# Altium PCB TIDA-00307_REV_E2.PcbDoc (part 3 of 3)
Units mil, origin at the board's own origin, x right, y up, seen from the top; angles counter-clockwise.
Board outline 2360 x 3725 mil, 4 copper layers (Top Layer, L2_GND-PLANE, L3_PWR-PLANE, Bottom Layer), stack 90 mil thick; 312 components, 149 nets, 674 pads, 257 vias.
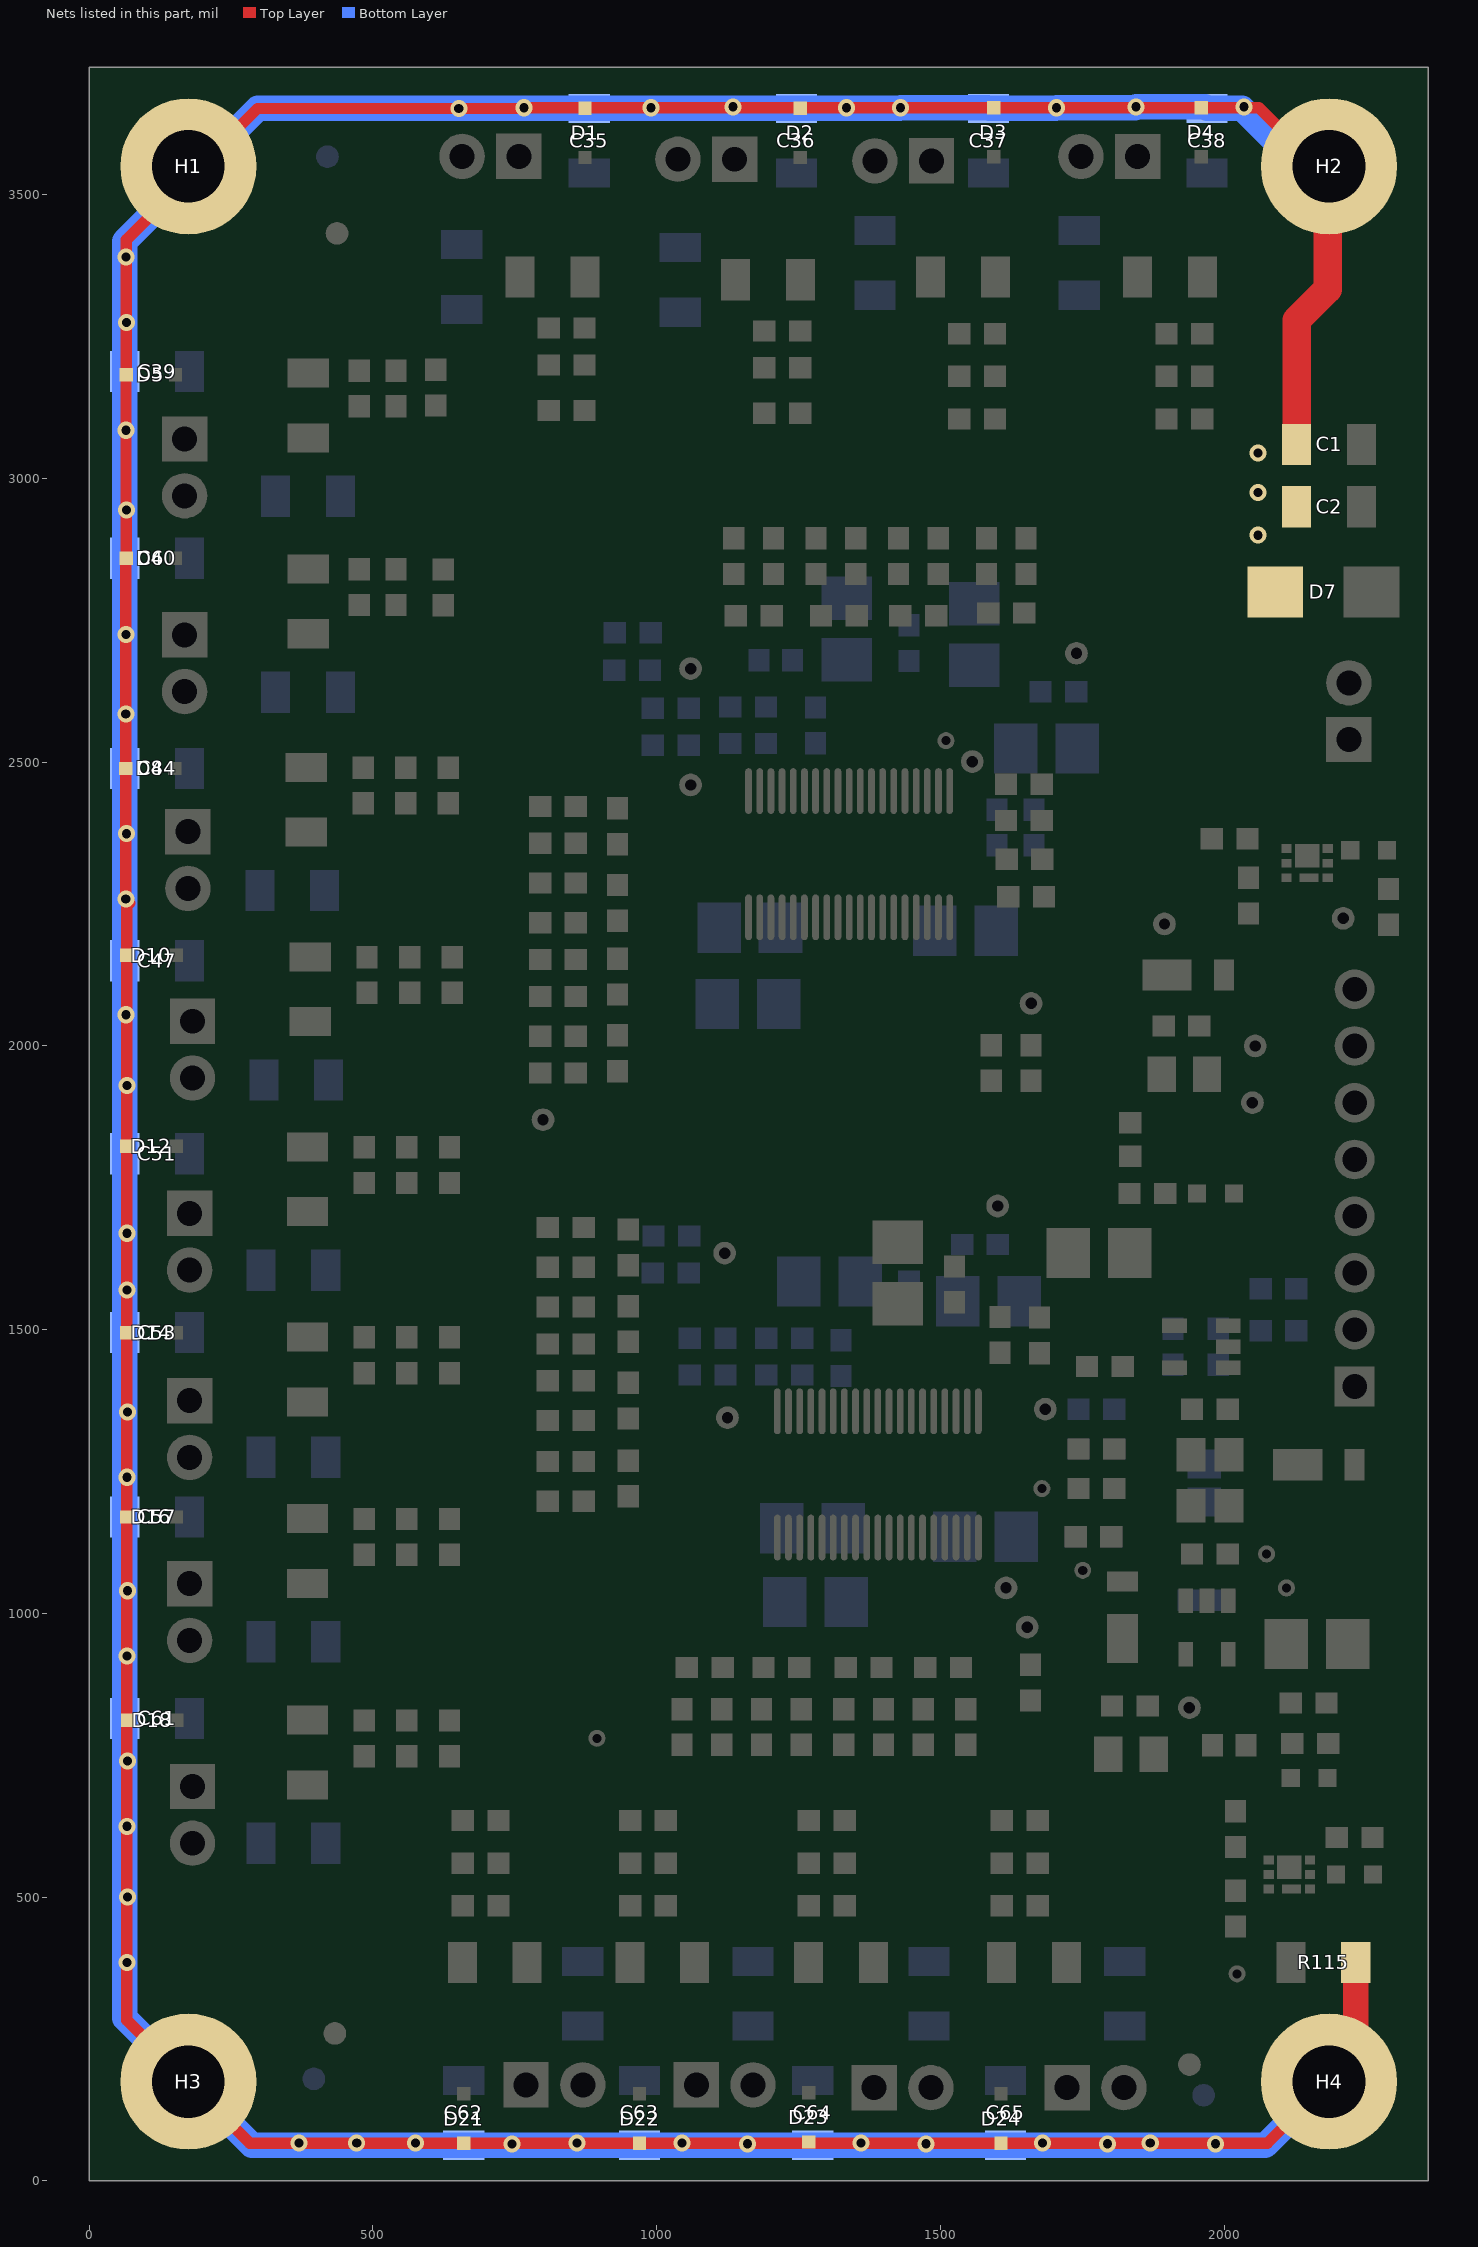
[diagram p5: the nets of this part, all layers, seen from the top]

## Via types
v1: diameter 30, hole 16, Top Layer to Bottom Layer, tented both sides, 155 vias
v2: diameter 24, hole 12, Top Layer to Bottom Layer, tented both sides, 102 vias

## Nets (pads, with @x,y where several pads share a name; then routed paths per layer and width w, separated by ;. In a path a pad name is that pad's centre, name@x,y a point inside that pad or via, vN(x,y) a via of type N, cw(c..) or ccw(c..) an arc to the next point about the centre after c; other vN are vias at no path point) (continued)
SGND1: C1.1 C2.1 C35.2 C36.2 C37.2 C38.2 C39.2 C40.2 C44.2 C47.2 C51.2 C53.2 C57.2 C61.2 C62.2 C63.2 C64.2 C65.2 D1.2 D2.2 D3.2 D4.2 D5.2 D6.2 D7.1 D8.2 D10.2 D12.2 D14.2 D16.2 D18.2 D21.2 D22.2 D23.2 D24.2 H1.1 H2.1 H3.1 H4.1 R115.2 | length 16058.1
  Top Layer w20: H2.1@2182.5,3532.5 2061.69,3653.31 D4.2@1960,3653.31 v1(1705,3653.31) D3.2@1594,3653.31 v1(1430,3653.31) v1(1335,3653.31) v1(990,3653.31) v1(766.5,3653.31) 765.28,3652.09 v1(651.5,3652.09) 297.09,3652.09 208,3563 65.69,3420.69 v1(65.69,3275) 65.69,3188.5 65,3187.8 v1(65,3085) 65,2945 v1(65.69,2944.31) D6.2@65.69,2859.5 64.69,2858.5 v1(64.69,2585) D8.2@64.69,2489 v1(64.69,2259) 71.69,2252 66.69,2247 D10.2@66.69,2160 v1(66.69,1930) D12.2@66.69,1823 v1(66.69,1670) D14.2@66.69,1495 v1(66.69,1240) D16.2@66.69,1170 v1(66.69,925) v1(66.69,625) v1(66.69,385) 66.69,283.31 H3.1@175,175 283.31,66.69 v1(370,66.69) v1(471.65,66.69) v1(575,66.69) D21.2@660,66.69 v1(860,66.69) D22.2@970,66.69 v1(1045,66.69) 1275,66.69 v1(1360,66.69) D24.2@1607,66.69 v1(1680,66.69) v1(1870,66.69) 2076.69,66.69 H4.1@2185,175
  Top Layer w45: H4.1@2185,175 2232.09,222.09 R115.2@2232.09,385
  Top Layer w50: C1.1@2127.91,3060 2127.91,3197.91 2127.91,3278.91 2182.5,3333.5 H2.1@2182.5,3532.5
  Bottom Layer w45: C40.2@62.91,2859.5 C39.2@62.91,3188.5 62.91,3417.91 208,3563 297.09,3652.09 v1(651.5,3652.09) C35.2@881.5,3652.09 C36.2@1246.5,3652.09 1428.78,3652.09 v1(1430,3653.31) 1583.78,3653.31 C37.2@1585,3652.09 1703.78,3652.09 v1(1705,3653.31) 1843.31,3653.31 v1(1845,3655) 1967.09,3655 C38.2@1970,3652.09 2032.09,3652.09 2159.17,3525 H2.1@2190,3525 ; C40.2@66.91,2859.5 62.91,2855.5 C44.2@62.91,2489 C47.2@62.91,2150 C51.2@62.91,1810 C53.2@62.91,1495 62.91,1240 C57.2@62.91,1170 62.91,925 C61.2@62.91,815 62.91,287.09 H3.1@175,175 287.09,62.91 575,62.91 C62.2@660,62.91 C63.2@970,62.91 1160,62.91 C64.2@1275,62.91 C65.2@1615,62.91 1795,62.91 2072.91,62.91 H4.1@2185,175
  other v1: 745,65 1160,65.47 1475,65.47 1795,65.47 1985,65.47 67.91,500 67.91,740 67.91,1040 67.91,1355 67.08,1570 65,2055 65.91,2374 65,2725 2060,2900 2060,2975 2060,3045 65,3390 1135,3655 2035,3655
pads on no net: FID1.1 FID2.1 FID3.1 FID4.1 FID5.1 FID6.1 U4.4

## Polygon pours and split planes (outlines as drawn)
SGND on Bottom Layer "Bottom Layer-No Net" (solid, remove dead copper, pour order 137): 410,1057.09 610,1057.09 630,1037.09 630,982.09 630,927.09 625,922.09 620,917.09 600,917.09 425,917.09 405,937.09 395,947.09 395,992.09 395,1042.09 410,1057.09
SGND on Bottom Layer "Bottom Layer-No Net" (solid, remove dead copper, pour order 142): 610,560 410,560 390,580 390,635 390,690 395,695 400,700 420,700 595,700 615,680 625,670 625,625 625,575 610,560
SGND on Bottom Layer "Bottom Layer-No Net" (solid, remove dead copper, pour order 141): 902.09,580 902.09,380 882.09,360 827.09,360 772.09,360 767.09,365 762.09,370 762.09,390 762.09,565 782.09,585 792.09,595 837.09,595 887.09,595 902.09,580
SGND on Bottom Layer "Bottom Layer-No Net" (solid, remove dead copper, pour order 140): 1212.09,580 1212.09,380 1192.09,360 1137.09,360 1082.09,360 1077.09,365 1072.09,370 1072.09,390 1072.09,565 1092.09,585 1102.09,595 1147.09,595 1197.09,595 1212.09,580
SGND on Bottom Layer "Bottom Layer-No Net" (solid, remove dead copper, pour order 139): 1517.09,580 1517.09,380 1497.09,360 1442.09,360 1387.09,360 1382.09,365 1377.09,370 1377.09,390 1377.09,565 1397.09,585 1407.09,595 1452.09,595 1502.09,595 1517.09,580
SGND on Bottom Layer "Bottom Layer-No Net" (solid, remove dead copper, pour order 138): 1872.09,585 1872.09,385 1852.09,365 1797.09,365 1742.09,365 1737.09,370 1732.09,375 1732.09,395 1732.09,570 1752.09,590 1762.09,600 1807.09,600 1857.09,600 1872.09,585
SGND on Bottom Layer "Bottom Layer-No Net" (solid, remove dead copper, pour order 128): 408,1373 548,1373 568,1353 568,1253 543,1228 428,1228 393,1260.09 393,1355.09
SGND on Bottom Layer "Bottom Layer-No Net" (solid, remove dead copper, pour order 129): 404,1704 544,1704 564,1684 564,1584 539,1559 424,1559 389,1591.09 389,1686.09
SGND on Bottom Layer "Bottom Layer-No Net" (solid, remove dead copper, pour order 105): 1605,1595 1740,1595 1770,1565 1775,1560 1775,1505 1775,1481.2 1756,1462.2 1753.25,1459.45 1674.06,1459.45 1625.55,1459.45 1605,1480 1600,1485 1600,1515 1600,1595
SGND on Bottom Layer "Bottom Layer-No Net" (solid, remove dead copper, pour order 97): 1729.33,2278.11 1588.61,2278.11 1576.35,2265.84 1564.33,2253.83 1564.33,2218.11 1564.33,2163.11 1574.33,2153.11 1579.33,2148.11 1634.33,2148.11 1714.33,2148.11 1724.33,2158.11 1754.33,2188.11 1754.33,2233.11 1754.33,2258.11 1734.33,2278.11 1729.33,2278.11
SGND on Bottom Layer "Bottom Layer-No Net" (solid, remove dead copper, pour order 94): 1100,1200 1250,1200 1260,1190 1260,1140 1260,985 1240,965 1235,960 1135,960 1100,960 1070,990 1065,995 1065,1120 1065,1170 1095,1200
SGND on Bottom Layer "Bottom Layer-No Net" (solid, remove dead copper, pour order 93): 1000,1385 1000.79,1384.21 1065,1384.21 1075.79,1395 1075,1395.79 1075,1445 1075,1540 1045,1570 1000,1570 995,1570 985,1560 980,1555 980,1500 980,1405 1000,1385
+5V_AVDD on Bottom Layer "Bottom Layer-No Net 1" (solid, remove dead copper, pour order 100): 1295,970 1295,1185 1305,1195 1345,1195 1415,1195 1430,1180 1445,1165 1445,1010 1445,975 1430,960 1420,950 1320,950 1315,950 1295,970
+3.3V on Bottom Layer "Bottom Layer-No Net 1" (solid, remove dead copper, pour order 104): 1460,975 1460,1165 1475,1180 1520,1180 1560,1180 1565,1175 1565,1115 1565,1005 1545,985 1530,970 1480,970 1465,970 1460,975
SGND on Bottom Layer "Bottom Layer-No Net" (solid, remove dead copper, pour order 110): 1255,1209.06 1434.06,1209.06 1435,1210 1455,1230 1455,1280 1440,1295 1255,1295 1240,1280 1225,1265 1225,1240 1225,1224.06 1240,1209.06 1240.94,1210 1255,1210
SGND on Bottom Layer "Bottom Layer-No Net" (solid, remove dead copper, pour order 136): 1487.09,3330 1487.09,3130 1467.09,3110 1412.09,3110 1357.09,3110 1352.09,3115 1347.09,3120 1347.09,3140 1347.09,3315 1367.09,3335 1377.09,3345 1422.09,3345 1472.09,3345 1487.09,3330
SGND on Bottom Layer "Bottom Layer-No Net" (solid, remove dead copper, pour order 135): 1837.09,3330 1837.09,3130 1817.09,3110 1762.09,3110 1707.09,3110 1702.09,3115 1697.09,3120 1697.09,3140 1697.09,3315 1717.09,3335 1727.09,3345 1772.09,3345 1822.09,3345 1837.09,3330
SGND on Bottom Layer "Bottom Layer-No Net" (solid, remove dead copper, pour order 134): 1156.5,3305 1156.5,3175 1146.5,3150 1036.5,3150 1016.5,3170 1016.5,3290 1043.58,3320 1138.58,3320
SGND on Bottom Layer "Bottom Layer-No Net" (solid, remove dead copper, pour order 133): 751.5,3305 751.5,3180 736.5,3160 631.5,3160 611.5,3180 611.5,3290 643.58,3320 731.5,3320
SGND on Bottom Layer "Bottom Layer-No Net" (solid, remove dead copper, pour order 132): 436,3058.5 561,3058.5 581,3038.5 581,2957 556,2928.5 446,2928.5 421,2950.58 421,3045.58
SGND on Bottom Layer "Bottom Layer-No Net" (solid, remove dead copper, pour order 131): 436,2718.5 556,2718.5 576,2703.5 576,2618.5 551,2588.5 451,2588.5 421,2610.58 421,2705.58
SGND on Bottom Layer "Bottom Layer-No Net" (solid, remove dead copper, pour order 130): 403,2364 543,2364 563,2344 563,2244 538,2219 423,2219 388,2251.09 388,2346.09
SGND on Bottom Layer "Bottom Layer-No Net" (solid, remove dead copper, pour order 127): 420,2040 585,2040 610,2010 610,1925 570,1905 425,1905 400,1927.09 400,2022.09
+5V_AVDD on Bottom Layer "Bottom Layer-No Net" (solid, remove dead copper, pour order 143): 1173,2013 1175,2015 1175,2245 1175,2255 1190,2270 1240,2270 1340,2270 1375,2235 1405,2205 1405,2160 1405,2055 1375,2025 1360,2010 1245,2010 1175,2010
SGND on Bottom Layer "Bottom Layer-No Net" (solid, remove dead copper, pour order 89): 1200,1825 1225,1800 1225,1725 1285,1650 1285,1535 1175,1535 1155,1550 1155,1680 1025,1680 1000,1700 1000,1775 1050,1825
SGND on Bottom Layer "Bottom Layer-No Net" (solid, remove dead copper, pour order 145): 1025,2010 1115,2010 1120,2015 1140,2035 1140,2045 1140,2265 1165,2290 1280,2290 1361.96,2290 1378.7,2306.74 1380,2308.04 1380,2345 1380,2365 1370,2375 1365,2380 1305,2380 1105,2380 1100,2375 1020,2295 1020,2105 1020,2015 1025,2010
SGND on Bottom Layer "Bottom Layer-No Net" (solid, remove dead copper, pour order 146): 1289.72,2758.11 1291.61,2760 1385,2760 1405,2760 1430,2735 1475,2735 1485,2745 1490,2750 1575,2750 1745,2750 1770,2775 1790,2795 1790,2855 1790,2880 1775,2895 1715,2895 1325,2895 1285,2855 1275.94,2845.94 1275.94,2785 1275.94,2771.89 1289.72,2758.11
+3.3V on Bottom Layer "Bottom Layer-No Net" (solid, remove dead copper, pour order 144): 1435,2255 1520,2255 1525,2250 1525,1980 1400,1855 1020,1855 950,1785 855,1785 835,1805 835,1940 885,1975 1355,1975 1425,2045 1425,2245
SGND on Bottom Layer "Bottom Layer-No Net" (solid, remove dead copper, pour order 76): 1857,2459 1738,2459 1725,2459 1705,2479 1704,2480 1704,2556 1704,2576 1717,2589 1722,2594 1808,2594 1860,2594 1866,2588 1875,2579 1875,2526 1875,2476 1859,2460
+5V_AVDD on Top Layer "Bottom Layer-No Net 1" (solid, remove dead copper, pour order 96): 1435,1010 1445,1020 1445,1060 1415,1090 1400,1090 1385,1075 1385,1040 1415,1010
SGND on Top Layer "Bottom Layer-No Net" (solid, remove dead copper, pour order 81): 1955,1380 1960,1375 1960,1085 1950,1075 1907,1075 1882,1040 1795,1040 1795,1070 1870,1140 1870,1365 1885,1380
NetC30_1 on Top Layer "Bottom Layer-No Net" (solid, remove dead copper, pour order 86): 1994,889 1994,950 1995,951 2033,951 2071,989 2136,989 2148,977 2148,887 2135,877 2136,759 2123,746 2029,746 2021,754 2021,782 2028,789 2066,789 2079,802 2079,875 2068,886 1998,886 1995,889
SGND on Top Layer "Bottom Layer-No Net" (solid, remove dead copper, pour order 77): 1990,340 1990,455 1995,460 2085,460 2100,475 2100,505 2110,515 2155,515 2160,510 2160,451 2141,429 2141,341
SGND on Top Layer "Bottom Layer-No Net" (solid, remove dead copper, pour order 103): 1545,1590 1545,1690 1545,1700 1500,1745 1485,1760 1330,1760 1285,1760 1225,1700 1220,1695 1220,1635 1220,1630 1235,1615 1440,1615 1490,1615 1500,1605 1515,1590 1545,1590
GND_EARTH on Top Layer "Bottom Layer-No Net" (solid, remove dead copper, pour order 99): 2164.88,2490 2165,2490.12 2165,2680 2210,2725 2210,2795 2210,2905 2215,2910 2220,2915 2220,2955 2220,3125 2225,3130 2230,3135 2270,3135 2295,3135 2305,3125 2310,3120 2310,3085 2310,2524.88 2275.12,2490 2164.88,2490
SGND1 on Top Layer "Bottom Layer-No Net" (solid, remove dead copper, pour order 98): 2030,3115 2140,3115 2150,3105 2155,3100 2155,3055 2155,2865 2140,2850 2140,2740 2140,2730 2130,2720 2125,2715 2065,2715 2055,2715 2035,2735 2030,2740 2030,2835 2030,3115
SGND on Top Layer "Bottom Layer-No Net" (solid, remove dead copper, pour order 91): 1730,855 1810,855 1815,855 1820,850 1820,815 1820,720 1810,710 1805,705 1755,705 1750,705 1720,735 1715,740 1715,840 1730,855
NetD20_1 on Top Layer "Bottom Layer-No Net" (solid, remove dead copper, pour order 74): 2170.83,529.58 2075.83,529.58 2070.83,534.58 2070.83,559.58 2070.83,574.58 2075.83,579.58 2095.83,579.58 2205.83,579.58 2215.83,569.58 2215.83,524.58 2185.83,524.58 2180.83,529.58 2170.83,529.58
+3.3V on Top Layer "Bottom Layer-No Net" (solid, remove dead copper, pour order 88): 1875,690 1980,690 1990,700 1995,705 1995,765 1995,830 1960,865 1915,865 1905,865 1880,890 1880,985 1880,995 1875,1000 1810,1000 1750,1000 1740,990 1730,980 1730,900 1730,880 1740,870 1785,870 1835,870 1845,860 1850,855 1850,820 1850,710 1870,690
SGND on Top Layer "Bottom Layer-No Net" (solid, remove dead copper, pour order 87): 2164,820 2164,866 2164,868 2178,882 2182,886 2182,909 2182,1050 2193,1061 2228,1061 2285,1061 2287,1059 2295,1051 2295,1038 2295,831 2273,809 2272,808 2192,808 2177,808 2165,820
SGND on Top Layer "Bottom Layer-No Net" (solid, remove dead copper, pour order 85): 1945,1865 1945,1955 1945,2060 1965,2080 1985,2100 1985,2135 1985,2160 1995,2170 2000,2175 2040,2175 2065,2175 2090,2150 2105,2135 2105,2090 2105,2070 2080,2045 2055,2045 2045,2045 2030,2030 2020,2020 2020,1935 2020,1875 2010,1865 2005,1860 1960,1860 1950,1860 1945,1865
SGND on Top Layer "Bottom Layer-No Net" (solid, remove dead copper, pour order 83): 1735,1415 1775,1415 1775,1580 1765,1590 1760,1595 1760,1635 1760,1670 1750,1680 1690,1680 1690,1570 1710,1550 1715,1545 1715,1455 1715,1435 1735,1415
NetC16_1 on Top Layer "Bottom Layer-No Net" (solid, remove dead copper, pour order 82): 1885,1445 1930,1445 1930,1420 1882.73,1420 1880,1420 1870,1410 1867.73,1407.73 1824,1407.73 1812.27,1407.73 1805,1415 1805,1445 1805,1815 1815,1825 1855,1825 1855,1725 1855,1615 1855,1475 1885,1445
+DC_IN on Top Layer "Bottom Layer-No Net" (solid, remove dead copper, pour order 80): 1985,1445 2055,1445 2065,1435 2065,1331.5 2080,1316.5 2158.5,1316.5 2170,1305 2170,1100 2160,1080 1985,1080
NetD15_2 on Top Layer "Bottom Layer-No Net" (solid, remove dead copper, pour order 79): 2215,1245 2215,1330 2190,1355 2185,1360 2185,1390 2185,1435 2195,1445 2225,1445 2270,1445 2275,1440 2275,1410 2275,1355 2250,1330 2248.25,1328.25 2248.25,1316.5 2248.25,1248.25 2245,1245 2215,1245
SGND on Top Layer "Bottom Layer-No Net" (solid, remove dead copper, pour order 78): 2095,2192 2030,2192 2025,2197 2025,2247 2030,2252 2075,2252 2120,2252 2130,2262 2135,2267 2135,2292 2135,2297 2140,2302 2145,2307 2180,2307 2190,2307 2195,2302 2195,2262 2195,2217 2170,2192 2100,2192
NetD9_1 on Top Layer "Bottom Layer-No Net" (solid, remove dead copper, pour order 75): 2190,2312 2095,2312 2090,2317 2090,2342 2090,2357 2095,2362 2115,2362 2225,2362 2235,2352 2235,2307 2205,2307 2200,2312 2190,2312
+5V_AVDD on Top Layer "Bottom Layer-No Net 1" (solid, remove dead copper, pour order 90): 1389.33,2178.11 1349.33,2178.11 1339.33,2178.11 1334.33,2173.11 1334.33,2143.11 1334.33,2133.11 1339.33,2128.11 1374.33,2128.11 1399.33,2128.11 1404.33,2133.11 1404.33,2158.11 1404.33,2173.11 1399.33,2178.11 1389.33,2178.11
+3.3V on Top Layer "Bottom Layer-No Net 1" (solid, remove dead copper, pour order 92): 1444.33,2168.11 1424.33,2168.11 1414.33,2158.11 1414.33,2098.11 1424.33,2088.11 1449.33,2088.11 1454.33,2088.11 1464.33,2078.11 1479.33,2078.11 1489.33,2088.11 1489.33,2103.11 1479.33,2113.11 1449.33,2143.11 1449.33,2158.11 1444.33,2163.11 1444.33,2168.11
+3.3V on Top Layer "Bottom Layer-No Net 1" (solid, remove dead copper, pour order 102): 1460,1005 1460,1050 1460,1075 1465,1080 1490,1080 1501.14,1080 1505.2,1075.94 1505,1075.75 1505,1045 1505,1000 1500,995 1465,995 1460,1000 1460,1010
SGND on Top Layer "Bottom Layer-No Net" (solid, remove dead copper, pour order 101): 1431.33,2395.11 1442.33,2395.11 1459.33,2378.11 1459.33,2343.11 1404.33,2308.11 1404.33,2282.87 1156.65,2282.87 1146.42,2293.11 1146.42,2380.2 1159.33,2393.11 1444.33,2393.11
SGND on Top Layer "Bottom Layer-No Net" (solid, remove dead copper, pour order 106): 1435,1189.88 1465,1240 1515,1240 1515,1280.12 1490.12,1305 1220,1305 1197.09,1275 1197.09,1210 1225,1190
SGND on Top Layer "Bottom Layer-No Net" (solid, remove dead copper, pour order 126): 465,580 465,750 485,770 595,770 605,760 605,585 585,560 485,560
SGND on Top Layer "Bottom Layer-No Net" (solid, remove dead copper, pour order 125): 465,935 465,1105 485,1125 595,1125 605,1115 605,940 585,915 485,915
SGND on Top Layer "Bottom Layer-No Net" (solid, remove dead copper, pour order 124): 455,1251.5 455,1421.5 475,1441.5 585,1441.5 595,1431.5 595,1256.5 575,1231.5 475,1231.5
SGND on Top Layer "Bottom Layer-No Net" (solid, remove dead copper, pour order 123): 445,1586.5 445,1756.5 465,1776.5 575,1776.5 585,1766.5 585,1591.5 565,1566.5 465,1566.5
SGND on Top Layer "Bottom Layer-No Net" (solid, remove dead copper, pour order 122): 1361.5,3295 1531.5,3295 1551.5,3275 1551.5,3165 1541.5,3155 1366.5,3155 1341.5,3175 1341.5,3275
SGND on Top Layer "Bottom Layer-No Net" (solid, remove dead copper, pour order 121): 1726.5,3285 1896.5,3285 1916.5,3265 1916.5,3155 1906.5,3145 1731.5,3145 1706.5,3165 1706.5,3265
SGND on Top Layer "Bottom Layer-No Net" (solid, remove dead copper, pour order 120): 460,1921.5 460,2091.5 480,2111.5 590,2111.5 600,2101.5 600,1926.5 580,1901.5 480,1901.5
SGND on Top Layer "Bottom Layer-No Net" (solid, remove dead copper, pour order 119): 448,2255.5 448,2425.5 468,2445.5 578,2445.5 588,2435.5 588,2260.5 568,2235.5 468,2235.5
SGND on Top Layer "Bottom Layer-No Net" (solid, remove dead copper, pour order 118): 581,2772 581,2602 561,2582 451,2582 441,2592 441,2767 461,2792 561,2792
SGND on Top Layer "Bottom Layer-No Net" (solid, remove dead copper, pour order 117): 581,3127 581,2957 561,2937 451,2937 441,2947 441,3122 461,3147 561,3147
SGND on Top Layer "Bottom Layer-No Net" (solid, remove dead copper, pour order 116): 810,3160 640,3160 620,3180 620,3290 630,3300 805,3300 830,3280 830,3180
SGND on Top Layer "Bottom Layer-No Net" (solid, remove dead copper, pour order 115): 1190,3150 1020,3150 1000,3170 1000,3280 1010,3290 1185,3290 1210,3270 1210,3170
SGND on Top Layer "Bottom Layer-No Net" (solid, remove dead copper, pour order 114): 893.5,445 723.5,445 703.5,465 703.5,575 713.5,585 888.5,585 913.5,565 913.5,465
SGND on Top Layer "Bottom Layer-No Net" (solid, remove dead copper, pour order 113): 1188.5,450 1018.5,450 998.5,470 998.5,580 1008.5,590 1183.5,590 1208.5,570 1208.5,470
SGND on Top Layer "Bottom Layer-No Net" (solid, remove dead copper, pour order 112): 1503.5,445 1333.5,445 1313.5,465 1313.5,575 1323.5,585 1498.5,585 1523.5,565 1523.5,465
SGND on Top Layer "Bottom Layer-No Net" (solid, remove dead copper, pour order 111): 1843.5,450 1673.5,450 1653.5,470 1653.5,580 1663.5,590 1838.5,590 1863.5,570 1863.5,470
+5V on Top Layer "Bottom Layer-No Net" (solid, remove dead copper, pour order 84): 1815,1850 1900,1850 1910,1860 1915,1865 1915,1920 1915,2070 1940,2095 1940,2170 1940,2330 1915,2355 1910,2360 1865,2360 1860,2360 1840,2340 1830,2330 1830,2220 1830,1935 1810,1915 1807.32,1912.32 1807.32,1866.5 1807.32,1857.68 1815,1850
+3.3V on L3_PWR-PLANE "Bottom Layer-No Net" (solid, remove dead copper, pour order 109): 224,3286 448,3521 1200,3525 1951,3524 2155.21,3306.21 2155,2965 1940,2770 905,2770 750,2580 749,2078 871,1958 1025,1958 1060,1918 1062,1774 1025,1725 1025,1005 1115,895 1385,895 1470,995 1470,1110 1505,1130 1790,1130 1850,1070 1920,1070 1990,1140 1990,1350 1835,1505 1835,2015 2000,2180 2000,2320 2041.5,2360 2245,2360 2300,2315 2295,465 1965,210 1235,215 480,215 230,485 225,1250 220,2005
+5V on L3_PWR-PLANE "Bottom Layer-No Net" (solid, remove dead copper, pour order 108): 1475,1195 1475,1605 1400,1675 1400,1785 1475,1855 1620,2000 1619,2549 1550,2620 1256,2620 1110,2372 1110,2061 1056,1992 880,1990 780,2090 780,2569 907,2730 1912,2729 1979,2655 1980,2405 1980,2195 1810,2025 1810,1495 1965,1340 1965,1155 1905,1095 1870,1095 1805,1155 1510,1155 1490,1180
+5V_AVDD on L3_PWR-PLANE "Bottom Layer-No Net" (solid, remove dead copper, pour order 107): 1530,2590 1590,2533 1590,2025 1360,1820 1360,1645 1435,1580 1440,1015 1420,990 1370,930 1145,930 1075,1000 1075,1730 1095,1770 1095,1995 1140,2061 1141,2356 1270,2590
SGND on L2_GND-PLANE "Bottom Layer-No Net" (solid, remove dead copper, pour order 95): 370,140 345,170 345,255 245,355 185,355 130,415 130,1785 135,2625 135,3120 136,3296 460,3604 500,3605 1932,3599 1986,3521 1970,3087 1969,2675 1968,2573 2042,2456 2097,2384 2165,2385 2290,2383 2328,2341 2327,2128 2326,358 2090,345 2020,290 1985,225 1982,142

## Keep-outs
Keep-Out Layer:
  lines w6: 20,20 20,3705 2340,3705 2340,20 20,20
  lines w10: 4950,3455 cw(c4950,3450) 4955,3450 ; 4950,3455 cw(c4950,3450) 4955,3450 ; 4950,3455 cw(c4950,3450) 4955,3450 ; 4950,3455 cw(c4950,3450) 4955,3450 ; 4950,3455 cw(c4950,3450) 4955,3450 ; 4950,3455 cw(c4950,3450) 4955,3450
  text ".Layer_Name" at 577,-858.49 h60

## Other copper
Top Layer:
  text ".Layer_Name" at 577,-858.49 h60
L2_GND-PLANE:
  pour cut-out: 918.71,156.24 906.55,144.08 726.68,146.85 726.98,145.45 727.09,130.97 726.09,116.97 918.71,116.97
  pour cut-out: 1218.71,156.24 1206.55,144.08 1026.68,146.85 1026.98,145.45 1027.09,130.97 1026.09,116.97 1218.71,116.97
  pour cut-out: 1532.21,151.24 1520.05,139.08 1340.18,141.85 1340.48,140.45 1340.59,125.97 1339.59,111.97 1532.21,111.97
  pour cut-out: 1872.21,151.24 1860.05,139.08 1680.18,141.85 1680.48,140.45 1680.59,125.97 1679.59,111.97 1872.21,111.97
  pour cut-out: 1699.16,3580.35 1711.32,3592.52 1891.19,3589.74 1890.89,3591.14 1890.78,3605.62 1891.78,3619.62 1699.16,3619.62
  pour cut-out: 1335.87,3572.73 1348.04,3584.89 1527.91,3582.12 1527.6,3583.52 1527.5,3598 1528.5,3612 1335.87,3612
  pour cut-out: 988.78,3575.61 1000.95,3587.77 1180.82,3585 1180.51,3586.4 1180.41,3600.88 1181.41,3614.88 988.78,3614.88
  pour cut-out: 608.78,3580.61 620.95,3592.77 800.82,3590 800.51,3591.4 800.41,3605.88 801.41,3619.88 608.78,3619.88
  pour cut-out: 155.39,2920.78 143.23,2932.95 146,3112.82 144.6,3112.51 130.12,3112.41 116.12,3113.41 116.12,2920.78
  pour cut-out: 155.39,2575.78 143.23,2587.95 146,2767.82 144.6,2767.51 130.12,2767.41 116.12,2768.41 116.12,2575.78
  pour cut-out: 161.21,2228.87 149.04,2241.04 151.82,2420.91 150.42,2420.6 135.94,2420.5 121.94,2421.5 121.94,2228.87
  pour cut-out: 169.27,1894.87 157.11,1907.04 159.88,2086.91 158.48,2086.6 144,2086.5 130,2087.5 130,1894.87
  pour cut-out: 164.27,1556.37 152.11,1568.54 154.88,1748.41 153.48,1748.1 139,1748 125,1749 125,1556.37
  pour cut-out: 164.27,1226.37 152.11,1238.54 154.88,1418.41 153.48,1418.1 139,1418 125,1419 125,1226.37
  pour cut-out: 164.27,903.93 152.11,916.09 154.88,1095.96 153.48,1095.66 139,1095.56 125,1096.56 125,903.93
  pour cut-out: 169.27,546.37 157.11,558.54 159.88,738.41 158.48,738.1 144,738 130,739 130,546.37
  pour cut-out: 1847.87,3516.87 1747.87,3516.87 1747.87,3567.3 1847.87,3567.3
  pour cut-out: 1484.59,3509.25 1384.59,3509.25 1384.59,3559.68 1484.59,3559.68
  pour cut-out: 1137.5,3512.13 1037.5,3512.13 1037.5,3562.56 1137.5,3562.56
  pour cut-out: 757.5,3517.13 657.5,3517.13 657.5,3567.56 757.5,3567.56
  pour cut-out: 218.87,3069.5 218.87,2969.5 168.44,2969.5 168.44,3069.5
  pour cut-out: 218.87,2724.5 218.87,2624.5 168.44,2624.5 168.44,2724.5
  pour cut-out: 224.69,2377.59 224.69,2277.59 174.26,2277.59 174.26,2377.59
  pour cut-out: 232.75,2043.59 232.75,1943.59 182.32,1943.59 182.32,2043.59
  pour cut-out: 227.75,1705.09 227.75,1605.09 177.32,1605.09 177.32,1705.09
  pour cut-out: 227.75,1375.09 227.75,1275.09 177.32,1275.09 177.32,1375.09
  pour cut-out: 227.75,1052.64 227.75,952.64 177.32,952.64 177.32,1052.64
  pour cut-out: 232.75,695.09 232.75,595.09 182.32,595.09 182.32,695.09
  pour cut-out: 1723.5,214.72 1823.5,214.72 1823.5,164.29 1723.5,164.29
  pour cut-out: 1383.5,214.72 1483.5,214.72 1483.5,164.29 1383.5,164.29
  pour cut-out: 1070,219.72 1170,219.72 1170,169.29 1070,169.29
  pour cut-out: 770,219.72 870,219.72 870,169.29 770,169.29
  pour cut-out: 1443.5,2330 1473.5,2330 1483.5,2320 1483.5,2297 1476.5,2290 1443.5,2290 1433.5,2300 1433.5,2320
  pour cut-out: 1495,1240 1505,1230 1505,1205 1495,1195 1470,1195 1460,1205 1460,1235 1465,1240
  text ".Layer_Name" at 612,-866 h60
L3_PWR-PLANE:
  text ".Layer_Name" at 640,-860 h60
Bottom Layer:
  text ".Layer_Name" at 577,-858.49 h60

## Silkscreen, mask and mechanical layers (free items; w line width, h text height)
Top Overlay:
  lines w6: 634.01,1064.3 610.26,1040.55 610.26,965.55 630.82,945 635,945 833.3,945 908.3,945 1005,945 1030,970 1030,1070 1020,1080 1015,1080 679.28,1080 ; 740,2505 741,2505 760,2486 ; 760,2793 760,2486 ; 779,2505 760,2486 ; 960,935 960,915 1005,870 ; 980,870 1005,870 ; 1005,895 1005,870 ; 1727,1033 1734,1033 1746,1045 ; 1918,687 1937,706 1937,796 ; 2324,2293 2332,2301 2332,2310 ; 990,730 1005,715 1585,715 1585,870 1015,870 990,845 990,730
  text ".Layer_Name" at 577,-858.49 h60
Bottom Overlay:
  text "AFE_MU" at 958,1047 h50
  text "TIDA-00307" at 1046,971 h50
  text "Rev E2" at 909,885 h50
  text ".Layer_Name" at 577,-858.49 h60
Top Paste:
  text ".Layer_Name" at 577,-858.49 h60
Bottom Paste:
  text ".Layer_Name" at 577,-858.49 h60
Top Solder:
  text ".Layer_Name" at 577,-858.49 h60
  text ".Layer_Name" at 577,-858.49 h60
Bottom Solder:
  text ".Layer_Name" at 577,-858.49 h60
Drill Guide:
  text ".Layer_Name" at 577,-858.49 h60
M1 Board Outline:
  the board outline again, w10
M2 Board Dimensions:
  rectangle: 124.5,-410.5 499.5,-285.5
  rectangle: -0.5,-285.5 124.5,-160.5
  lines w7: -0.5,-285.5 999.5,-285.5 ; 124.5,-410.5 124.5,-160.5 ; 249.5,-410.5 249.5,-160.5 ; 499.5,-410.5 499.5,-160.5 ; 749.5,-410.5 749.5,-160.5 ; -0.5,-410.5 -0.5,-160.5 999.5,-160.5 999.5,-410.5 -0.5,-410.5
  lines w10: -0.5,-475.5 -0.5,-455.5 ; 59.5,-485.5 -0.5,-465.5 ; 59.5,-445.5 -0.5,-465.5 ; 223.58,-465.5 -0.5,-465.5 ; 775.42,-465.5 999.5,-465.5 ; 939.5,-485.5 999.5,-465.5 ; 939.5,-445.5 999.5,-465.5 ; 999.5,-475.5 999.5,-455.5
  text "1000 (mil)" at 233.58,-501.49 h60
  text ".Layer_Name" at 577,-858.49 h60
M3 3D STEP Top:
  text ".Layer_Name" at 577,-858.49 h60
M4 3D STEP Bottom:
  text ".Layer_Name" at 577,-858.49 h60
M5 Assembly Top:
  lines w10: -292,-930.17 6308,-930.17 ; -292,-726.83 6310,-726.83 ; -292,-523.5 -292,-1133.5 3713,-1133.5 6310,-1133.5 6310,-523.5 -291.5,-523.5 -291.5,-1133.5 1284,-1133.5 ; 2173,-1133.5 2173,-523.5 ; 3735,-726 3735,-522.67 ; 4280,-726.83 4280,-523.5 ; 4902,-1140 4902,-937.17
  text "COMPONENTS MARKED 'DNP' SHOULD NOT BE POPULATED." at 1153.5,-318.5 h60
  text "ASSEMBLY VARIANT:" at 1153,-434 h60
  text ".VariantName" at 2189,-434 h60
  text "PCB VIEWED FROM TOP SIDE" at -228.5,-655.67 h60
  text "BOARD #:" at 2248,-655.67 h60
  text "TIDA-00307" at 2793.5,-655.67 h60
  text "SVN REV:" at 4476,-655.67 h60
  text ".VersionControl_RevNumber" at 4982,-655.67 h60
  text "REV: E2" at 3805,-660 h60
  text "Assembly Top" at 671,-856 h60
  text "IGNORE ->" at -228.5,-858.49 h60
  text "PLOT NAME =" at -228.5,-1064.34 h60
  text ".plot_File_Name" at 577,-1064.34 h60
  text "GENERATED    :" at 2250,-1064.34 h60
  text ".Print_Date" at 3119.5,-1064.34 h60
  text ".Print_Time" at 3848.5,-1064.34 h60
  text "TEXAS INSTRUMENTS" at 5113,-1064.34 h60
M6 Assembly Bottom:
  lines w10: -292.5,-727.33 6309.5,-727.33 ; -290.5,-930.67 6309.5,-930.67 ; 1115.5,-1140.5 1115.5,-937.67 ; 1737.5,-727.33 1737.5,-524 ; 2236,-723 2236,-519.67 ; 3844.5,-1134 3844.5,-524 ; 4733.5,-1134 6309,-1134 6309,-524 -292.5,-524 -292.5,-1134 2304.5,-1134 6309.5,-1134 6309.5,-524
  text "COMPONENTS MARKED 'DNP' SHOULD NOT BE POPULATED." at 6102,-318 h60
  text ".VariantName" at 5058,-434 h60
  text "ASSEMBLY VARIANT:" at 6097,-434 h60
  text "REV: E2" at 2173,-655 h60
  text ".VersionControl_RevNumber" at 1035.5,-656.17 h60
  text "SVN REV:" at 1541.5,-656.17 h60
  text "TIDA-00307" at 3224,-656.17 h60
  text "BOARD #:" at 3769.5,-656.17 h60
  text "PCB VIEWED FROM BOTTOM SIDE" at 6246,-656.17 h60
  text "Assembly Bottom" at 1410,-847 h60
  text "IGNORE ->" at 2547.85,-858.49 h60
  text "TEXAS INSTRUMENTS" at 904.5,-1064.84 h60
  text ".Print_Time" at 2169,-1064.84 h60
  text ".Print_Date" at 2898,-1064.84 h60
  text "GENERATED    :" at 3767.5,-1064.84 h60
  text ".plot_File_Name" at 5440.5,-1064.84 h60
  text "PLOT NAME =" at 6246,-1064.84 h60
M9 Title Sheet:
  drawing of 57 lines, arcs and shapes, not listed
  text "1" at 739.84,8036.5 h70
  text "2" at 3235.5,8036.5 h70
  text "3" at 5724.84,8036.5 h70
  text "4" at 8231.51,8036.5 h70
  text "5" at 10730.5,8036.5 h70
  text "6" at 13235.5,8036.5 h70
  text "A" at -416.5,6893.5 h70
  text "A" at 14383.5,6893.5 h70
  text "B" at -416.5,4513.5 h70
  text "B" at 14383.5,4513.5 h70
  text "C" at -416.5,2138.5 h70
  text "C" at 14383.5,2138.5 h70
  text "PROJECT TITLE:" at 11343.5,277.5 h45
  text "AFE_MU" at 11393.5,144.17 h70
  text "DESIGNED FOR:" at 11343.5,-23.5 h45
  text ".PRJ_Customer" at 11393.5,-163.5 h70
  text "D" at -416.5,-231.5 h70
  text "D" at 14383.5,-231.5 h70
  text "FILE NAME:" at 11343.5,-323.5 h45
  text "TIDA-00307" at 11393.5,-443.5 h70
  text "Texas Instruments (TI) and/or its licensors do not warrant the accuracy or completeness of this specification" at 6374,-605.34 h45
  text "ENGINEER:" at 11343.5,-613.5 h45
  text "LAYOUT BY:" at 12848.5,-613.5 h45
  text "or any information contained therein. TI and/or its licensors do not warrant that this design will meet" at 6329.01,-718 h45
  text "Sreenivas K." at 11393.5,-768.49 h70
  text "the specifications, will be suitable for your application or fit for any particular purpose, or will operate in" at 6329.01,-830.67 h45
  text "ALTIUM DESIGNER VERSION:" at 12848.5,-923.5 h45
  text "an implementation. TI and/or its licensors do not warrant that the design is production worthy. You should" at 6329.01,-943.33 h45
  text "completely validate and test your design implementation to confirm the system functionality for your application." at 6374,-1056 h45
  text ".print_Scale" at 11393.5,-1056.83 h70
  text ".Application_BuildNumber" at 12899,-1056.83 h70
  text "1" at 739.84,-1263.5 h70
  text "2" at 3235.5,-1263.5 h70
  text "3" at 5724.84,-1263.5 h70
  text "4" at 8231.51,-1263.5 h70
  text "5" at 10730.5,-1263.5 h70
  text "6" at 13235.5,-1263.5 h70
M10 Fab Notes:
  drawing of 212 lines, arcs and shapes, not listed
  text "DESIGN INFORMATION" at 12381.02,6810 h60
  text "(REFER ALSO ARRAY/PANEL PROFILING INFORMATION)" at 12019.46,6648.29 h60
  text "BOARD SIZE" at 11333.46,6644 h60
  text "2360MIL" at 11795.78,6516.18 h60
  text "X" at 12301.46,6516.18 h60
  text "3725MIL" at 12532.78,6516.18 h60
  text "Number of Layers :" at 11691.46,6399 h60
  text "4" at 12786.27,6389 h60
  text "MIN. TRACK WIDTH:" at 11691.46,6260 h60
  text "8" at 12787.7,6260 h60
  text "MIL" at 12942.46,6260 h60
  text "7.87" at 12692,6131 h60
  text "MIN. CLEARANCE:" at 11691.46,6128 h60
  text "MIL" at 12942.46,6128 h60
  text "MIN. VIA PAD SIZE:" at 11691.46,5996 h60
  text "24" at 12757.71,5996 h60
  text "MIL" at 12942.46,5996 h60
  text "0.152mm (6MIL)" at 12386.46,5854.29 h60
  text "EXTERNAL" at 13137,5852 h60
  text "MINIMUM ANNULAR RING" at 11362.23,5850 h60
  text "PER" at 11562.23,5732 h60
  text "IPC-D-275 CLASS 2 LEVEL C" at 11782.23,5732 h60
  text "MIL, HOLES" at 13270.46,5619.71 h60
  text "+/-" at 12878,5619 h60
  text "+/-" at 13732,5619 h60
  text "REGISTRATION TOLERANCES:" at 11362.23,5614 h60
  text "METAL" at 12562,5614 h60
  text "5" at 13138.2,5614 h60
  text "3" at 13971.2,5614 h60
  text "MIL" at 14087.46,5614 h60
  text "IMPEDANCE CONTROLLED:NO" at 11561.46,5516 h60
  text "MATERIAL:" at 11332.46,5324.54 h60
  text "FR-4 High Tg" at 12318.9,5184.21 h60
  text "FR-408" at 11753.46,5175.64 h60
  text "X" at 12165.46,5175.64 h60
  text "OTHER" at 13241.46,5175.64 h60
  text "63 MIL (1.6mm) +/-10%" at 12073.56,5012.92 h60
  text "THICKNESS:" at 11407.23,5008.64 h60
  text "X" at 11945.4,5008.64 h60
  text "OTHER" at 13358.46,5008.64 h60
  text "TOLERANCE:" at 11407.23,4850.64 h60
  text "X" at 12246.53,4850.64 h60
  text "ANSI IPC-6012 TYPE 3 CLASS 2" at 12433.48,4850.64 h60
  text "OTHER +/-" at 12433.46,4694.64 h60
  text "BOW & TWIST:" at 11407.23,4537.64 h60
  text "X" at 12246.53,4537.64 h60
  text "ANSI IPC-6012 TYPE 3 CLASS 2" at 12433.48,4537.64 h60
  text "OTHER +/-" at 12433.46,4379.13 h60
  text "COPPER THICKNESS (FINISHED):" at 11332.46,4243.64 h60
  text "1.4MIL (1oz)" at 12212.46,4090.92 h60
  text "2MIL (1.4oz)" at 12979.46,4090.92 h60
  text "2.8MIL (2oz)" at 13706.46,4090.92 h60
  text "OUTER:" at 11689.46,4086.64 h60
  text "X" at 12084,4086 h60
  text "1.4MIL (1oz)" at 12212.46,3933.92 h60
  text "2.8MIL (2oz)" at 12979.46,3933.92 h60
  text "N/A" at 13706,3934.29 h60
  text "INNER SIGNAL:" at 11400.38,3929.64 h60
  text "X" at 12085.42,3929.64 h60
  text "DRILLING:" at 11332.46,3790.64 h60
  text "REFERENCE:" at 11407.23,3673.64 h60
  text "X" at 12055.46,3673.64 h60
  text "AS SHOWN" at 12242.46,3673.64 h60
  text "X" at 12956.46,3673.64 h60
  text "NC_DRILL FILES" at 13093.46,3673.64 h60
  text "PTH MIN COPPER THICKNESS:" at 11407.23,3515.64 h60
  text "X" at 12757.46,3515.64 h60
  text "1MIL" at 12894.46,3515.64 h60
  text "OTHER" at 13391.46,3515.64 h60
  text "BOARD FINISH:" at 11332.46,3356.64 h60
  text "SILKSCREEN:" at 11487.68,3238.64 h60
  text "X" at 12436.46,3238.64 h60
  text "TOP" at 12562.46,3238.64 h60
  text "X" at 12946.46,3238.64 h60
  text "BOTTOM" at 13073.46,3238.64 h60
  text "SILKSCREEN COLOR:" at 11486.01,3072.64 h60
  text "X" at 12433.75,3072.64 h60
  text "WHITE" at 12560.79,3072.64 h60
  text "OTHER" at 13071.79,3072.64 h60
  text "SOLDER RESIST COLOR:" at 11592.01,2921.64 h60
  text "GREEN" at 12286.79,2762.44 h60
  text "X" at 12049,2750 h60
  text "BLUE" at 12857,2744 h60
  text "OTHER" at 13306,2740 h60
  text "IMMERSION GOLD (ENIG)" at 12393.46,2553.92 h60
  text "ENEPIG" at 13731,2550.64 h60
  text "SURFACE FINISH:" at 11332.46,2549.64 h60
  text "X" at 12206.51,2549.64 h60
  text "IMM. TIN/SILVER OR EQUIV" at 11662,2392.64 h60
  text "OTHER" at 13093.46,2392.64 h60
  text "ARRAY/PANEL:" at 11332.46,2213.64 h60
  text "CUT AND TRIM PER MECH LAYER 1" at 12393.46,2209.35 h60
  text "N.C. ROUTE" at 12393.46,2057.64 h60
  text "X" at 13072.46,2057.64 h60
  text "V. SCORE" at 13259.46,2057.64 h60
  text "CERTIFICATION:" at 11332.46,1920.64 h60
  text "MATERIALS AND WORKMANSHIP FOR ALL PCBS" at 12057.46,1920.64 h60
  text "TO MEET OR EXCEED THE REQUIREMENTS OF:" at 12057.46,1822.64 h60
  text "X" at 11683.96,1686.13 h60
  text "ANSI IPC-A-600F CLASS ->" at 11822.96,1686.13 h60
  text "X" at 13462.02,1686.13 h60
  text "2" at 13580.96,1686.14 h60
  text "1" at 13265.96,1684.64 h60
  text "3" at 13934.96,1684.64 h60
  text "X" at 11686.02,1526.64 h60
  text "UL 94V-0" at 11822.96,1526.64 h60
  text "X" at 12498.02,1526.64 h60
  text "RoHS" at 12634.96,1526.64 h60
  text "OTHER" at 13279.36,1526.64 h60
  text "PER ORDER" at 13676.42,1526.64 h60
  text "ADDITIONAL REQUIREMENTS:" at 11332.46,1385.64 h60
  text "MICROSECTION:" at 11407.23,1270.64 h60
  text "YES" at 12312.96,1270.64 h60
  text "REQUIRED" at 13174.46,1114.49 h60
  text "BARE BOARD ELEC. TEST:" at 11407.23,1111.64 h60
  text "NONE" at 12712.96,1111.64 h60
  text "X" at 13047.46,1111.64 h60
  text "PER ORDER" at 13766.46,1111.64 h60
  text "MANUFACTURER'S UL:" at 11407.23,954.64 h60
  text "RAIL" at 12572.96,950.35 h60
  text "METAL" at 13064.77,950.35 h60
  text "X" at 13440,950 h60
  text "SILK" at 13576.46,950.35 h60
M11 Gerber Information:
  lines w10: -292,-930.17 6308,-930.17 ; -292,-726.83 6310,-726.83 ; -292,-523.5 -292,-1133.5 3713,-1133.5 6310,-1133.5 6310,-523.5 -291.5,-523.5 -291.5,-1133.5 1284,-1133.5 ; 2173,-1133.5 2173,-523.5 ; 3690,-730 3690,-526.67 ; 4280,-726.83 4280,-523.5 ; 4902,-1140 4902,-937.17
  text "ALL ARTWORK VIEWED FROM TOP SIDE" at -228.5,-655.67 h60
  text "BOARD #:" at 2248,-655.67 h60
  text "SVN REV:" at 4476,-655.67 h60
  text ".VersionControl_RevNumber" at 4982,-655.67 h60
  text "REV: E2" at 3785,-657 h60
  text "TIDA-00307" at 2720,-660 h60
  text "LAYER NAME =" at -228.5,-858.49 h60
  text "PLOT NAME =" at -228.5,-1064.34 h60
  text ".plot_File_Name" at 577,-1064.34 h60
  text "GENERATED    :" at 2250,-1064.34 h60
  text ".Print_Date" at 3119.5,-1064.34 h60
  text ".Print_Time" at 3848.5,-1064.34 h60
  text "TEXAS INSTRUMENTS" at 5113,-1064.34 h60
M12 Stackup:
  lines w6: 11297,7707.5 14198,7707.5 ; 11297,7816 14198,7816 ; 11237,7024 ccw(c11272,7024) 11272,6989 14223,6989 ccw(c14223,7024) 14258,7024 14258,7908 ccw(c14223,7908) 14223,7943 11272,7943 ccw(c11272,7908) 11237,7908 11237,7024
  text "Layer Stack Up Detail for: TIDA-00307.PcbDoc" at 11297,7844.1 h48
  text "Layer" at 11297,7775.5 h25
  text "Gerber" at 12310.81,7775.5 h25
  text "Copper" at 12985.59,7775.5 h25
  text "Dielectric" at 13701.19,7775.5 h25
  text "Name" at 11297,7725.5 h25
  text "Document" at 12310.81,7725.5 h25
  text "Thickness" at 12985.59,7725.5 h25
  text "Material" at 13701.19,7725.5 h25
  text "Top Solder Mask" at 11297,7654.81 h35
  text "(.GTS)" at 12310.81,7654.81 h35
  text "Solder Resist" at 13701.19,7654.81 h35
  text "Top Layer" at 11297,7555.44 h35
  text "(.GTL)" at 12310.81,7555.44 h35
  text "1.4mil" at 12985.59,7555.44 h35
  text "FR-4" at 13701.19,7505.75 h35
  text "L2_GND-PLANE" at 11297,7456.06 h35
  text "(.G1)" at 12310.81,7456.06 h35
  text "1.4mil" at 12985.59,7456.06 h35
  text "FR-4" at 13701.19,7406.38 h35
  text "L3_PWR-PLANE" at 11297,7356.69 h35
  text "(.G2)" at 12310.81,7356.69 h35
  text "1.4mil" at 12985.59,7356.69 h35
  text "FR-4" at 13701.19,7307 h35
  text "Bottom Layer" at 11297,7257.31 h35
  text "(.GBL)" at 12310.81,7257.31 h35
  text "1.4mil" at 12985.59,7257.31 h35
  text "Bottom Solder Mask" at 11297,7157.94 h35
  text "(.GBS)" at 12310.81,7157.94 h35
  text "Solder Resist" at 13701.19,7157.94 h35
M13 Component Bodies Top:
  text ".Layer_Name" at 577,-858.49 h60
M14 Component Bodies Bottom:
  text ".Layer_Name" at 577,-858.49 h60
M15 Courtyards Top:
  text ".Layer_Name" at 577,-858.49 h60
M16 Courtyards Bottom:
  text ".Layer_Name" at 577,-858.49 h60
Drill Drawing:
  text ".legend" at 4281.25,609.45 h60
  text "Drill Table" at 4280,455 h60
  text "FOR 12MIL DRILL +0/-12MIL" at 4342.7,284.2 h60
  text "FOR 16MIL DRILL +0/-16MIL" at 4337.55,161.3 h60
  text ".Layer_Name" at 577,-858.49 h60

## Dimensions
2360,3725 to 2360,0 on M2 Board Dimensions
0,3725 to 2360,3725 on M2 Board Dimensions
2360,0 to 2360,3725 on Drill Drawing
0,3725 to 2360,3725 on Drill Drawing
2185,175 to 2185,3550 on Drill Drawing
175,3550 to 2185,3550 on Drill Drawing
